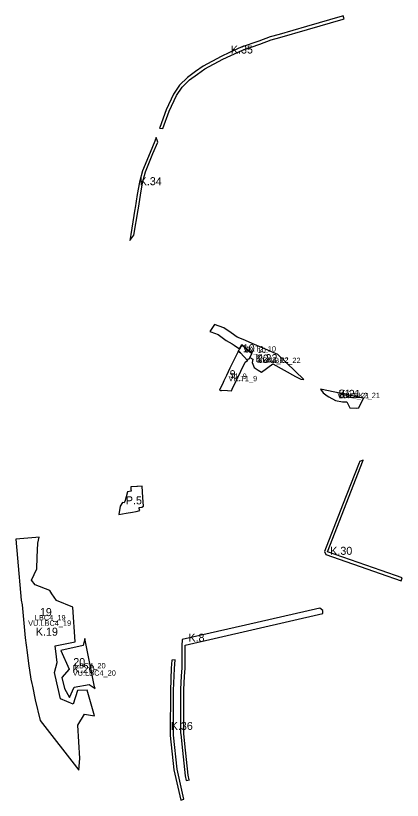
# Model space of a CAD drawing. Extents: x -521969 to -519862, y -1142171 to -1140238.
# Drawn here: x -520586 to -519862, y -1141720 to -1140250 of the extents above; entities that cross this region are included whole.
import ezdxf

# ---------------------------------------------------------------- set-up
doc = ezdxf.new("R2010")
doc.units = 0
for name, color, linetype in [('96110023', 7, 'Continuous'), ('96111023', 7, 'Continuous'), ('96120023', 7, 'Continuous'), ('96140023', 7, 'Continuous'), ('96203023', 7, 'Continuous'), ('96205023', 7, 'Continuous'), ('ID_VPO', 7, 'Continuous'), ('ID_VPS', 7, 'Continuous')]:
    doc.layers.add(name, color=color, linetype=linetype)

msp = doc.modelspace()

# ---------------------------------------------------------------- linework, layer by layer
at = {"layer": '96110023'}
msp.add_lwpolyline([(-520392.71, -1141184.99), (-520378.86, -1141182.41), (-520366.93, -1141180.34), (-520360.34, -1141179.18), (-520353.47, -1141177.71), (-520354.34, -1141173.71), (-520354.71, -1141171.83), (-520349.86, -1141171.48), (-520346.65, -1141169.3), (-520347.81, -1141152.92), (-520347.61, -1141152.91), (-520349.11, -1141131.64), (-520357.95, -1141132.21), (-520359.15, -1141132.28), (-520370.32, -1141133), (-520369.99, -1141138.16), (-520369.8, -1141141.08), (-520376.18, -1141142.7), (-520381.05, -1141158.47), (-520382.54, -1141163.3), (-520383.02, -1141163.15), (-520385.67, -1141162.39), (-520390.51, -1141169.6), (-520392.71, -1141184.99)], dxfattribs=at)
at = {"layer": '96111023'}
for points in [[(-520316.15, -1140459.86), (-520316.75, -1140461.52), (-520310.52, -1140461.93), (-520298.27, -1140429.16), (-520285.01, -1140400.23), (-520274.33, -1140384.38), (-520260.24, -1140370.94), (-520245.33, -1140359.99), (-520231.71, -1140350.36), (-520198.24, -1140332), (-520183.06, -1140324.86), (-520161.16, -1140315.09), (-520128.63, -1140303.97), (-520107.24, -1140295.95), (-520091.03, -1140291.29), (-520039.59, -1140276.29), (-519972.75, -1140256.9), (-519970.54, -1140256.24), (-519972.39, -1140250.5), (-519972.61, -1140250.6), (-519974.44, -1140251.14), (-520041.27, -1140270.53), (-520092.7, -1140285.53), (-520109.13, -1140290.25), (-520130.65, -1140298.32), (-520163.36, -1140309.5), (-520185.56, -1140319.41), (-520200.96, -1140326.65), (-520234.9, -1140345.26), (-520248.84, -1140355.12), (-520264.1, -1140366.33), (-520278.94, -1140380.49), (-520290.26, -1140397.28), (-520303.81, -1140426.86)], [(-520370.36, -1140660.47), (-520371.84, -1140671.63), (-520364.42, -1140661.36), (-520356.59, -1140613.91), (-520356.14, -1140611.39), (-520352.4, -1140586.73), (-520348.21, -1140563.43), (-520342.62, -1140543.01), (-520328.73, -1140508.82), (-520319.85, -1140487.51), (-520320.44, -1140485.82), (-520322.93, -1140478.71), (-520325.43, -1140485.29), (-520334.28, -1140506.54), (-520348.31, -1140541.08), (-520354.07, -1140562.1), (-520358.32, -1140585.75), (-520362.06, -1140610.41), (-520362.5, -1140612.89)], [(-520222.55, -1140842.43), (-520220.12, -1140842.45), (-520206.43, -1140847.59), (-520196.46, -1140855.08), (-520191.59, -1140858.73), (-520180.27, -1140865.22), (-520176.48, -1140867.88), (-520166.62, -1140874.78), (-520162.5, -1140867.24), (-520152.09, -1140876.15), (-520143.83, -1140883.35), (-520147.23, -1140890.72), (-520141.61, -1140894.1), (-520143.26, -1140900.05), (-520139.09, -1140909.85), (-520131.65, -1140914.52), (-520125.39, -1140918.45), (-520104.55, -1140902.75), (-520061.67, -1140926.36), (-520059.41, -1140927.64), (-520055.67, -1140929.56), (-520051.93, -1140931.48), (-520046.33, -1140932.29), (-520094.9, -1140885.23), (-520122.13, -1140873.55), (-520138.6, -1140866.49), (-520159.88, -1140857.36), (-520170.98, -1140852.6), (-520182.58, -1140844.72), (-520196.23, -1140835.45), (-520213.5, -1140828.96), (-520217.49, -1140834.9)], [(-519999.3, -1140964.63), (-519986.94, -1140971.3), (-519974.08, -1140974.02), (-519965.47, -1140973.69), (-519959.93, -1140985.31), (-519947.03, -1140986.05), (-519943.51, -1140985.08), (-519934.8, -1140967.08), (-520015.17, -1140949.95), (-520009.84, -1140957.29), (-520002.28, -1140962.91)], [(-520585.84, -1141231.02), (-520582.4, -1141266.58), (-520575.29, -1141345.21), (-520573.91, -1141353.97), (-520567.96, -1141415.92), (-520564.35, -1141443.41), (-520561.66, -1141463.92), (-520557.24, -1141493.24), (-520555.49, -1141501.75), (-520554.45, -1141506.79), (-520549.23, -1141532.17), (-520539.75, -1141570.9), (-520467.83, -1141664.2), (-520465.85, -1141641.84), (-520469.63, -1141579.9), (-520457.06, -1141558.71), (-520438.57, -1141562.32), (-520451.9, -1141513.8), (-520469.99, -1141514.94), (-520478.09, -1141540.57), (-520501.99, -1141530.25), (-520512.09, -1141486.67), (-520513.39, -1141481.08), (-520508.38, -1141462.38), (-520509.69, -1141451.35), (-520512.06, -1141431.3), (-520474.23, -1141423.42), (-520479.06, -1141358.55), (-520509.58, -1141346.13), (-520517.94, -1141333.55), (-520521.95, -1141327.46), (-520549.32, -1141316.76), (-520556.25, -1141307.68), (-520546.39, -1141287.04), (-520545.37, -1141264.63), (-520544.19, -1141238.83), (-520541.94, -1141227.47), (-520548.16, -1141227.97)], [(-520277.2, -1141512.43), (-520277.03, -1141563.71), (-520276.93, -1141594.74), (-520276.82, -1141595.78), (-520274.84, -1141614.95), (-520268.73, -1141674.23), (-520266.52, -1141683.24), (-520260.66, -1141681.95), (-520260.68, -1141681.85), (-520262.8, -1141673.2), (-520268.87, -1141614.33), (-520270.85, -1141595.16), (-520270.93, -1141594.41), (-520271.03, -1141563.69), (-520271.2, -1141512.61), (-520269.68, -1141488.31), (-520268.69, -1141472.55), (-520268.47, -1141429.64), (-520010.61, -1141370.65), (-520010.91, -1141364.55), (-520016.19, -1141360.33), (-520155.8, -1141392.1), (-520274.28, -1141419.2), (-520274.48, -1141431.01), (-520274.69, -1141472.35), (-520275.67, -1141487.93)], [(-520501.13, -1141439.65), (-520485.81, -1141474.99), (-520499.43, -1141490.33), (-520494.54, -1141511.04), (-520485.33, -1141527.78), (-520476.51, -1141508.33), (-520448.25, -1141503.52), (-520436.83, -1141511), (-520438.53, -1141507.64), (-520456.11, -1141417.28), (-520459.35, -1141430.33)], [(-520276.36, -1141720.39), (-520270.75, -1141718.04), (-520283.67, -1141662.22), (-520290.53, -1141598.43), (-520290.52, -1141595.71), (-520290.19, -1141514.57), (-520288.42, -1141473.23), (-520287.25, -1141456.97), (-520293.35, -1141458.14), (-520294.41, -1141472.89), (-520296.19, -1141514.43), (-520296.52, -1141595.69), (-520296.53, -1141598.74), (-520289.6, -1141663.22)]]:
    msp.add_lwpolyline(points, close=True, dxfattribs=at)
for points in [[(-519942.77, -1141088.03), (-519973.57, -1141167.53), (-520007.53, -1141254.06), (-520004.78, -1141260.17), (-519903.26, -1141295.46), (-519864.09, -1141309.46)], [(-519861.86, -1141303.89), (-519901.27, -1141289.8), (-520002.16, -1141254.73), (-519935.26, -1141083.16), (-519941.89, -1141085.78)], [(-519941.9, -1141085.78), (-519942.77, -1141088.03)], [(-519941.89, -1141085.78), (-519941.9, -1141085.78)], [(-519864.09, -1141309.46), (-519861.86, -1141303.89)]]:
    msp.add_lwpolyline(points, dxfattribs=at)
at = {"layer": '96120023'}
for points in [[(-520162.5, -1140867.24), (-520166.62, -1140874.78)], [(-520152.09, -1140876.15), (-520162.5, -1140867.24)], [(-520164.55, -1140881.96), (-520168.95, -1140879.03), (-520170.08, -1140881.1), (-520178.74, -1140898.05), (-520184.7, -1140910.65), (-520191.17, -1140924.29), (-520193, -1140928.16), (-520196.08, -1140934.67), (-520197.39, -1140937.44), (-520204.29, -1140951.99), (-520201.3, -1140953.32), (-520201.27, -1140953.32), (-520200.79, -1140952.24), (-520189.01, -1140952.86), (-520181.77, -1140953.24), (-520180.26, -1140950.09), (-520156.19, -1140899.86), (-520151.68, -1140896.26)], [(-520166.62, -1140874.78), (-520167.79, -1140876.9), (-520168.95, -1140879.03), (-520164.55, -1140881.96)], [(-520164.55, -1140881.96), (-520151.68, -1140896.26)], [(-520151.68, -1140896.26), (-520164.55, -1140881.96)], [(-520143.83, -1140883.35), (-520152.09, -1140876.15)], [(-520151.68, -1140896.26), (-520149.94, -1140892.73), (-520148.74, -1140894), (-520148.27, -1140892.97), (-520147.23, -1140890.72), (-520143.83, -1140883.35)]]:
    msp.add_lwpolyline(points, dxfattribs=at)
at = {"layer": '96140023'}
for points in [[(-520222.55, -1140842.43), (-520220.12, -1140842.45), (-520206.43, -1140847.59), (-520196.46, -1140855.08), (-520191.59, -1140858.73), (-520180.27, -1140865.22), (-520176.48, -1140867.88), (-520166.62, -1140874.78), (-520162.5, -1140867.24), (-520152.09, -1140876.15), (-520143.83, -1140883.35), (-520147.23, -1140890.72), (-520141.61, -1140894.1), (-520143.26, -1140900.05), (-520139.09, -1140909.85), (-520131.65, -1140914.52), (-520125.39, -1140918.45), (-520104.55, -1140902.75), (-520061.67, -1140926.36), (-520059.41, -1140927.64), (-520055.67, -1140929.56), (-520051.93, -1140931.48), (-520046.33, -1140932.29), (-520094.9, -1140885.23), (-520122.13, -1140873.55), (-520138.6, -1140866.49), (-520159.88, -1140857.36), (-520170.98, -1140852.6), (-520182.58, -1140844.72), (-520196.23, -1140835.45), (-520213.5, -1140828.96), (-520217.49, -1140834.9), (-520222.55, -1140842.43)], [(-519999.3, -1140964.63), (-519986.94, -1140971.3), (-519974.08, -1140974.02), (-519965.47, -1140973.69), (-519959.93, -1140985.31), (-519947.03, -1140986.05), (-519943.51, -1140985.08), (-519934.8, -1140967.08), (-520015.17, -1140949.95), (-520009.84, -1140957.29), (-520002.28, -1140962.91), (-519999.3, -1140964.63)], [(-520501.13, -1141439.65), (-520485.81, -1141474.99), (-520499.43, -1141490.33), (-520494.54, -1141511.04), (-520485.33, -1141527.78), (-520476.51, -1141508.33), (-520448.25, -1141503.52), (-520436.83, -1141511), (-520438.53, -1141507.64), (-520456.11, -1141417.28), (-520459.35, -1141430.33), (-520501.13, -1141439.65)]]:
    msp.add_lwpolyline(points, dxfattribs=at)
msp.add_lwpolyline([(-520585.84, -1141231.02), (-520582.4, -1141266.58), (-520575.29, -1141345.21), (-520573.91, -1141353.97), (-520567.96, -1141415.92), (-520564.35, -1141443.41), (-520561.66, -1141463.92), (-520557.24, -1141493.24), (-520555.49, -1141501.75), (-520554.45, -1141506.79), (-520549.23, -1141532.17), (-520539.75, -1141570.9), (-520467.83, -1141664.2), (-520465.85, -1141641.84), (-520469.63, -1141579.9), (-520457.06, -1141558.71), (-520438.57, -1141562.32), (-520451.9, -1141513.8), (-520469.99, -1141514.94), (-520478.09, -1141540.57), (-520501.99, -1141530.25), (-520512.09, -1141486.67), (-520513.39, -1141481.08), (-520508.38, -1141462.38), (-520509.69, -1141451.35), (-520512.06, -1141431.3), (-520474.23, -1141423.42), (-520479.06, -1141358.55), (-520509.58, -1141346.13), (-520517.94, -1141333.55), (-520521.95, -1141327.46), (-520549.32, -1141316.76), (-520556.25, -1141307.68), (-520546.39, -1141287.04), (-520545.37, -1141264.63), (-520544.19, -1141238.83), (-520541.94, -1141227.47), (-520548.16, -1141227.97)], close=True, dxfattribs=at)
at = {"layer": '96203023'}
for points in [[(-520162.5, -1140867.24), (-520166.62, -1140874.78)], [(-520152.09, -1140876.15), (-520162.5, -1140867.24)], [(-520164.55, -1140881.96), (-520168.95, -1140879.03), (-520170.08, -1140881.1), (-520178.74, -1140898.05), (-520184.7, -1140910.65), (-520191.17, -1140924.29), (-520193, -1140928.16), (-520196.08, -1140934.67), (-520197.39, -1140937.44), (-520204.29, -1140951.99), (-520201.3, -1140953.32), (-520201.27, -1140953.32), (-520200.79, -1140952.24), (-520189.01, -1140952.86), (-520181.77, -1140953.24), (-520180.26, -1140950.09), (-520156.19, -1140899.86), (-520151.68, -1140896.26)], [(-520166.62, -1140874.78), (-520167.79, -1140876.9), (-520168.95, -1140879.03), (-520164.55, -1140881.96)], [(-520151.68, -1140896.26), (-520164.55, -1140881.96)], [(-520164.55, -1140881.96), (-520151.68, -1140896.26)], [(-520143.83, -1140883.35), (-520152.09, -1140876.15)], [(-520151.68, -1140896.26), (-520149.94, -1140892.73), (-520148.74, -1140894), (-520148.27, -1140892.97), (-520147.23, -1140890.72), (-520143.83, -1140883.35)]]:
    msp.add_lwpolyline(points, dxfattribs=at)
at = {"layer": '96205023'}
for points in [[(-520217.49, -1140834.9), (-520222.55, -1140842.43)], [(-520213.5, -1140828.96), (-520217.49, -1140834.9)], [(-520182.58, -1140844.72), (-520196.23, -1140835.45), (-520213.5, -1140828.96)], [(-520222.55, -1140842.43), (-520220.12, -1140842.45), (-520206.43, -1140847.59), (-520196.46, -1140855.08)], [(-520196.46, -1140855.08), (-520191.59, -1140858.73)], [(-520170.98, -1140852.6), (-520182.58, -1140844.72)], [(-520051.93, -1140931.48), (-520046.33, -1140932.29), (-520094.9, -1140885.23), (-520122.13, -1140873.55), (-520138.6, -1140866.49), (-520159.88, -1140857.36), (-520170.98, -1140852.6)], [(-520191.59, -1140858.73), (-520180.27, -1140865.22)], [(-520180.27, -1140865.22), (-520176.48, -1140867.88)], [(-520176.48, -1140867.88), (-520166.62, -1140874.78)], [(-520166.62, -1140874.78), (-520162.5, -1140867.24), (-520152.09, -1140876.15)], [(-520152.09, -1140876.15), (-520143.83, -1140883.35)], [(-520143.83, -1140883.35), (-520147.23, -1140890.72)], [(-520147.23, -1140890.72), (-520141.61, -1140894.1), (-520143.26, -1140900.05)], [(-520143.26, -1140900.05), (-520139.09, -1140909.85), (-520131.65, -1140914.52)], [(-520125.39, -1140918.45), (-520104.55, -1140902.75), (-520061.67, -1140926.36), (-520059.41, -1140927.64), (-520055.67, -1140929.56)], [(-520131.65, -1140914.52), (-520125.39, -1140918.45)], [(-520055.67, -1140929.56), (-520051.93, -1140931.48)], [(-519934.8, -1140967.08), (-520015.17, -1140949.95)], [(-520015.17, -1140949.95), (-520009.84, -1140957.29)], [(-520009.84, -1140957.29), (-520002.28, -1140962.91)], [(-520002.28, -1140962.91), (-519999.3, -1140964.63)], [(-519999.3, -1140964.63), (-519986.94, -1140971.3)], [(-519986.94, -1140971.3), (-519974.08, -1140974.02)], [(-519947.03, -1140986.05), (-519943.51, -1140985.08), (-519934.8, -1140967.08)], [(-519974.08, -1140974.02), (-519965.47, -1140973.69), (-519959.93, -1140985.31), (-519947.03, -1140986.05)], [(-520456.11, -1141417.28), (-520459.35, -1141430.33)], [(-520436.83, -1141511), (-520438.53, -1141507.64), (-520456.11, -1141417.28)], [(-520459.35, -1141430.33), (-520501.13, -1141439.65), (-520485.81, -1141474.99)], [(-520485.81, -1141474.99), (-520499.43, -1141490.33)], [(-520499.43, -1141490.33), (-520494.54, -1141511.04)], [(-520494.54, -1141511.04), (-520485.33, -1141527.78)], [(-520485.33, -1141527.78), (-520476.51, -1141508.33), (-520448.25, -1141503.52)], [(-520448.25, -1141503.52), (-520436.83, -1141511)]]:
    msp.add_lwpolyline(points, dxfattribs=at)
msp.add_lwpolyline([(-520585.84, -1141231.02), (-520582.4, -1141266.58), (-520575.29, -1141345.21), (-520573.91, -1141353.97), (-520567.96, -1141415.92), (-520564.35, -1141443.41), (-520561.66, -1141463.92), (-520557.24, -1141493.24), (-520555.49, -1141501.75), (-520554.45, -1141506.79), (-520549.23, -1141532.17), (-520539.75, -1141570.9), (-520467.83, -1141664.2), (-520465.85, -1141641.84), (-520469.63, -1141579.9), (-520457.06, -1141558.71), (-520438.57, -1141562.32), (-520451.9, -1141513.8), (-520469.99, -1141514.94), (-520478.09, -1141540.57), (-520501.99, -1141530.25), (-520512.09, -1141486.67), (-520513.39, -1141481.08), (-520508.38, -1141462.38), (-520509.69, -1141451.35), (-520512.06, -1141431.3), (-520474.23, -1141423.42), (-520479.06, -1141358.55), (-520509.58, -1141346.13), (-520517.94, -1141333.55), (-520521.95, -1141327.46), (-520549.32, -1141316.76), (-520556.25, -1141307.68), (-520546.39, -1141287.04), (-520545.37, -1141264.63), (-520544.19, -1141238.83), (-520541.94, -1141227.47), (-520548.16, -1141227.97)], close=True, dxfattribs=at)

# ---------------------------------------------------------------- texts
at = {"layer": '96110023'}
msp.add_text('P.5', height=15, rotation=0, dxfattribs=at).set_placement((-520379.53, -1141165.94))
at = {"layer": '96111023'}
for s, rotation, p in [('K.35', 0, (-520182.81, -1140321.37)), ('K.34', 360, (-520353.62, -1140568.05)), ('K.22', 360, (-520136.89, -1140899.56)), ('K.21', 0, (-519981.15, -1140966.43)), ('K.30', 0, (-519996.81, -1141260.44)), ('K.19', 360, (-520548.07, -1141412.04)), ('K.20', 0, (-520479.25, -1141482.03))]:
    msp.add_text(s, height=15, rotation=rotation, dxfattribs=at).set_placement(p)
for s, p in [('K.8', (-520262.4, -1141423.12)), ('K.36', (-520295.42, -1141588.58))]:
    msp.add_text(s, height=15, dxfattribs=at).set_placement(p)
at = {"layer": '96120023'}
for s, p in [('T2_10', (-520156.61, -1140882.23)), ('T1_9', (-520184.63, -1140930.8))]:
    msp.add_text(s, height=10, rotation=0, dxfattribs=at).set_placement(p)
at = {"layer": '96140023'}
for s, rotation, p in [('LBK2_22', 0, (-520131.52, -1140900.55)), ('LBK2_21', 0, (-519980.73, -1140967.08)), ('LBC4_19', 360, (-520550.02, -1141383.29)), ('LBC4_20', 360, (-520475.05, -1141473.29))]:
    msp.add_text(s, height=10, rotation=rotation, dxfattribs=at).set_placement(p)
at = {"layer": '96203023'}
for s, p in [('VK.T2_10', (-520159.87, -1140879.62)), ('VK.T1_9', (-520187.29, -1140935.26))]:
    msp.add_text(s, height=10, rotation=360, dxfattribs=at).set_placement(p)
at = {"layer": '96205023'}
for s, rotation, p in [('VU.LBK2_22', 360, (-520132.22, -1140901.28)), ('VU.LBK2_21', 360, (-519983.53, -1140966.95)), ('VU.LBC4_19', 0, (-520562.56, -1141393.43)), ('VU.LBC4_20', 0, (-520478.91, -1141486.89))]:
    msp.add_text(s, height=10, rotation=rotation, dxfattribs=at).set_placement(p)
at = {"layer": 'ID_VPO'}
for s, rotation, p in [('22', 0, (-520134.17, -1140900.29)), ('19', 360, (-520540.57, -1141375.31)), ('20', 0, (-520477.97, -1141468.99))]:
    msp.add_text(s, height=15, rotation=rotation, dxfattribs=at).set_placement(p)
msp.add_text('21', height=15, dxfattribs=at).set_placement((-519980.75, -1140965.93))
at = {"layer": 'ID_VPS'}
for s, p in [('10', (-520160.65, -1140880.9)), ('9', (-520185.12, -1140929.6))]:
    msp.add_text(s, height=15, rotation=0, dxfattribs=at).set_placement(p)

doc.saveas('drawing.dxf')
